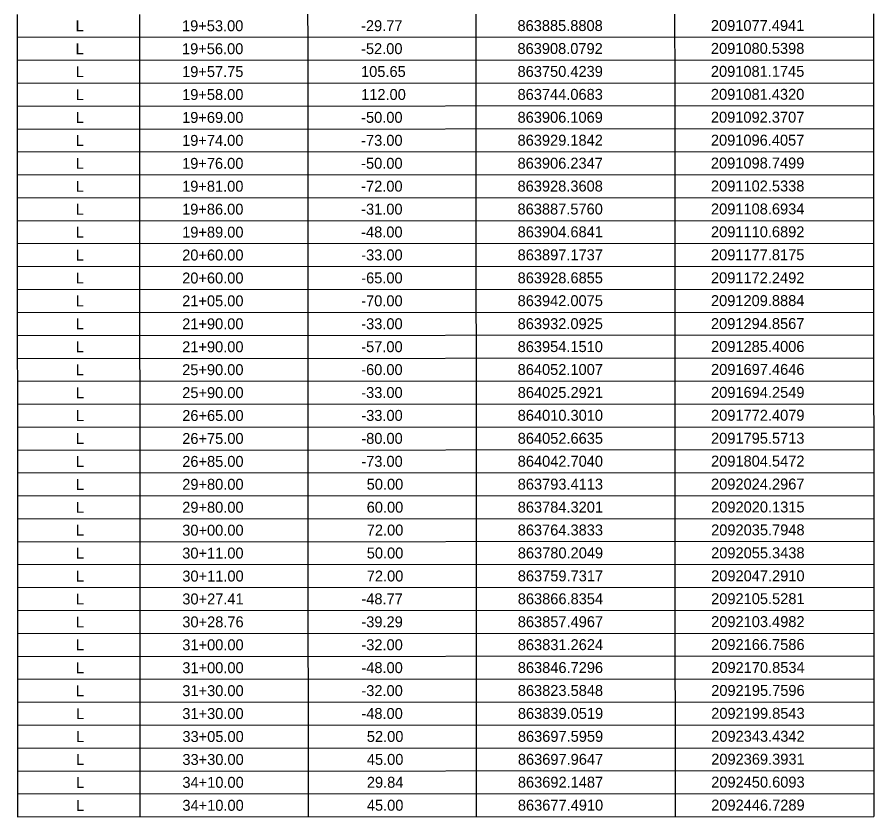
# Model space of a CAD drawing. Extents: x 2093228 to 2098328, y 861854 to 865154.
# Drawn here: x 2094060 to 2095157, y 863101 to 864125 of the extents above; entities that cross this region are included whole.
import ezdxf

# ---------------------------------------------------------------- set-up
doc = ezdxf.new("R2010")
doc.units = 0
doc.layers.add('CTL Sheet Table Cell', color=7, linetype='Continuous')
doc.layers.add('CTL Sheet Text', color=7, linetype='Continuous')

msp = doc.modelspace()

# ---------------------------------------------------------------- linework, layer by layer
at = {"layer": 'CTL Sheet Table Cell'}
for p, q in [((2094060, 864128.6), (2094060, 864099.2)), ((2094216.6, 864128.6), (2094216.6, 864099.3)), ((2094431.9, 864128.7), (2094432, 864099.4)), ((2094647.3, 864128.9), (2094647.3, 864099.5)), ((2094901.7, 864129), (2094901.7, 864099.6)), ((2095156.2, 864129.1), (2095156.2, 864099.7)), ((2094060, 864099.2), (2095156.2, 864099.7)), ((2094060, 864099.2), (2094060.1, 864069.8)), ((2094216.6, 864099.3), (2094216.7, 864069.9)), ((2094432, 864099.4), (2094432, 864070)), ((2094647.3, 864099.5), (2094647.3, 864070.1)), ((2094901.7, 864099.6), (2094901.8, 864070.3)), ((2095156.2, 864099.7), (2095156.2, 864070.4)), ((2094060.1, 864069.8), (2095156.2, 864070.4)), ((2094060.1, 864069.8), (2094060.1, 864040.5)), ((2094216.7, 864069.9), (2094216.7, 864040.6)), ((2094432, 864070), (2094432, 864040.7)), ((2094647.3, 864070.1), (2094647.3, 864040.8)), ((2094901.8, 864070.3), (2094901.8, 864040.9)), ((2095156.2, 864070.4), (2095156.2, 864041)), ((2094060.1, 864040.5), (2095156.2, 864041)), ((2094060.1, 864040.5), (2094060.1, 864011.1)), ((2094216.7, 864040.6), (2094216.7, 864011.2)), ((2094432, 864040.7), (2094432, 864011.3)), ((2094647.3, 864040.8), (2094647.3, 864011.4)), ((2094901.8, 864040.9), (2094901.8, 864011.5)), ((2095156.2, 864041), (2095156.3, 864011.7)), ((2094060.1, 864011.1), (2095156.3, 864011.7)), ((2094060.1, 864011.1), (2094060.1, 863981.8)), ((2094216.7, 864011.2), (2094216.7, 863981.8)), ((2094432, 864011.3), (2094432, 863981.9)), ((2094647.3, 864011.4), (2094647.3, 863982)), ((2094901.8, 864011.5), (2094901.8, 863982.2)), ((2095156.3, 864011.7), (2095156.3, 863982.3)), ((2094060.1, 863981.8), (2095156.3, 863982.3)), ((2094060.1, 863981.8), (2094060.1, 863952.4)), ((2094216.7, 863981.8), (2094216.7, 863952.5)), ((2094432, 863981.9), (2094432, 863952.6)), ((2094647.3, 863982), (2094647.4, 863952.7)), ((2094901.8, 863982.2), (2094901.8, 863952.8)), ((2095156.3, 863982.3), (2095156.3, 863952.9)), ((2094060.1, 863952.4), (2095156.3, 863952.9)), ((2094060.1, 863952.4), (2094060.1, 863923)), ((2094216.7, 863952.5), (2094216.7, 863923.1)), ((2094432, 863952.6), (2094432, 863923.2)), ((2094647.4, 863952.7), (2094647.4, 863923.3)), ((2094901.8, 863952.8), (2094901.8, 863923.4)), ((2095156.3, 863952.9), (2095156.3, 863923.6)), ((2094060.1, 863923), (2095156.3, 863923.6)), ((2094060.1, 863923), (2094060.1, 863893.7)), ((2094216.7, 863923.1), (2094216.7, 863893.8)), ((2094432, 863923.2), (2094432.1, 863893.9)), ((2094647.4, 863923.3), (2094647.4, 863894)), ((2094901.8, 863923.4), (2094901.8, 863894.1)), ((2095156.3, 863923.6), (2095156.3, 863894.2)), ((2094060.1, 863893.7), (2095156.3, 863894.2)), ((2094901.8, 863894.1), (2094901.9, 863864.7)), ((2095156.3, 863894.2), (2095156.3, 863864.8)), ((2094060.1, 863893.7), (2094060.2, 863864.3)), ((2094216.7, 863893.8), (2094216.8, 863864.4)), ((2094432.1, 863893.9), (2094432.1, 863864.5)), ((2094647.4, 863894), (2094647.4, 863864.6)), ((2094060.2, 863864.3), (2095156.3, 863864.8)), ((2094060.2, 863864.3), (2094060.2, 863835)), ((2094216.8, 863864.4), (2094216.8, 863835)), ((2094432.1, 863864.5), (2094432.1, 863835.1)), ((2094647.4, 863864.6), (2094647.4, 863835.2)), ((2094901.9, 863864.7), (2094901.9, 863835.4)), ((2095156.3, 863864.8), (2095156.3, 863835.5)), ((2094060.2, 863835), (2095156.3, 863835.5)), ((2094060.2, 863835), (2094060.2, 863805.6)), ((2094216.8, 863835), (2094216.8, 863805.7)), ((2094432.1, 863835.1), (2094432.1, 863805.8)), ((2094647.4, 863835.2), (2094647.4, 863805.9)), ((2094901.9, 863835.4), (2094901.9, 863806)), ((2095156.3, 863835.5), (2095156.4, 863806.1)), ((2094060.2, 863805.6), (2095156.4, 863806.1)), ((2094060.2, 863805.6), (2094060.2, 863776.2)), ((2094216.8, 863805.7), (2094216.8, 863776.3)), ((2094432.1, 863805.8), (2094432.1, 863776.4)), ((2094647.4, 863805.9), (2094647.4, 863776.5)), ((2094901.9, 863806), (2094901.9, 863776.6)), ((2095156.4, 863806.1), (2095156.4, 863776.8)), ((2094060.2, 863776.2), (2095156.4, 863776.8)), ((2094060.2, 863776.2), (2094060.2, 863746.9)), ((2094216.8, 863776.3), (2094216.8, 863746.9)), ((2094432.1, 863776.4), (2094432.1, 863747)), ((2094647.4, 863776.5), (2094647.4, 863747.2)), ((2094901.9, 863776.6), (2094901.9, 863747.3)), ((2095156.4, 863776.8), (2095156.4, 863747.4)), ((2094060.2, 863746.9), (2095156.4, 863747.4)), ((2094060.2, 863746.9), (2094060.2, 863717.5)), ((2094216.8, 863746.9), (2094216.8, 863717.6)), ((2094432.1, 863747), (2094432.1, 863717.7)), ((2094647.4, 863747.2), (2094647.5, 863717.8)), ((2094901.9, 863747.3), (2094901.9, 863717.9)), ((2095156.4, 863747.4), (2095156.4, 863718)), ((2094060.2, 863717.5), (2095156.4, 863718)), ((2094060.2, 863717.5), (2094060.2, 863688.1)), ((2094216.8, 863717.6), (2094216.8, 863688.2)), ((2094432.1, 863717.7), (2094432.2, 863688.3)), ((2094647.5, 863717.8), (2094647.5, 863688.4)), ((2094901.9, 863717.9), (2094901.9, 863688.6)), ((2095156.4, 863718), (2095156.4, 863688.7)), ((2094060.2, 863688.1), (2095156.4, 863688.7)), ((2094060.2, 863688.1), (2094060.3, 863658.8)), ((2094216.8, 863688.2), (2094216.9, 863658.9)), ((2094432.2, 863688.3), (2094432.2, 863659)), ((2094647.5, 863688.4), (2094647.5, 863659.1)), ((2094901.9, 863688.6), (2094902, 863659.2)), ((2095156.4, 863688.7), (2095156.4, 863659.3)), ((2094060.3, 863658.8), (2095156.4, 863659.3)), ((2094060.3, 863658.8), (2094060.3, 863629.4)), ((2094216.9, 863658.9), (2094216.9, 863629.5)), ((2094432.2, 863659), (2094432.2, 863629.6)), ((2094647.5, 863659.1), (2094647.5, 863629.7)), ((2094902, 863659.2), (2094902, 863629.8)), ((2095156.4, 863659.3), (2095156.4, 863630)), ((2094060.3, 863629.4), (2095156.4, 863630)), ((2094060.3, 863629.4), (2094060.3, 863600.1)), ((2094216.9, 863629.5), (2094216.9, 863600.1)), ((2094432.2, 863629.6), (2094432.2, 863600.2)), ((2094647.5, 863629.7), (2094647.5, 863600.3)), ((2094902, 863629.8), (2094902, 863600.5)), ((2095156.4, 863630), (2095156.5, 863600.6)), ((2094060.3, 863600.1), (2095156.5, 863600.6)), ((2094060.3, 863600.1), (2094060.3, 863570.7)), ((2094216.9, 863600.1), (2094216.9, 863570.8)), ((2094432.2, 863600.2), (2094432.2, 863570.9)), ((2094647.5, 863600.3), (2094647.5, 863571)), ((2094902, 863600.5), (2094902, 863571.1)), ((2095156.5, 863600.6), (2095156.5, 863571.2)), ((2094060.3, 863570.7), (2095156.5, 863571.2)), ((2094060.3, 863570.7), (2094060.3, 863541.3)), ((2094216.9, 863570.8), (2094216.9, 863541.4)), ((2094432.2, 863570.9), (2094432.2, 863541.5)), ((2094647.5, 863571), (2094647.5, 863541.6)), ((2094902, 863571.1), (2094902, 863541.7)), ((2095156.5, 863571.2), (2095156.5, 863541.9)), ((2094060.3, 863541.3), (2095156.5, 863541.9)), ((2094060.3, 863541.3), (2094060.3, 863512)), ((2094216.9, 863541.4), (2094216.9, 863512.1)), ((2094432.2, 863541.5), (2094432.2, 863512.2)), ((2094647.5, 863541.6), (2094647.6, 863512.3)), ((2094902, 863541.7), (2094902, 863512.4)), ((2095156.5, 863541.9), (2095156.5, 863512.5)), ((2094060.3, 863512), (2095156.5, 863512.5)), ((2094060.3, 863512), (2094060.3, 863482.6)), ((2094216.9, 863512.1), (2094216.9, 863482.7)), ((2094432.2, 863512.2), (2094432.3, 863482.8)), ((2094647.6, 863512.3), (2094647.6, 863482.9)), ((2094902, 863512.4), (2094902, 863483)), ((2095156.5, 863512.5), (2095156.5, 863483.1)), ((2094060.3, 863482.6), (2095156.5, 863483.1)), ((2094060.3, 863482.6), (2094060.4, 863453.3)), ((2094216.9, 863482.7), (2094217, 863453.3)), ((2094432.3, 863482.8), (2094432.3, 863453.4)), ((2094647.6, 863482.9), (2094647.6, 863453.5)), ((2094902, 863483), (2094902.1, 863453.7)), ((2095156.5, 863483.1), (2095156.5, 863453.8)), ((2094060.4, 863453.3), (2095156.5, 863453.8)), ((2094060.4, 863453.3), (2094060.4, 863423.9)), ((2094217, 863453.3), (2094217, 863424)), ((2094432.3, 863453.4), (2094432.3, 863424.1)), ((2094647.6, 863453.5), (2094647.6, 863424.2)), ((2094902.1, 863453.7), (2094902.1, 863424.3)), ((2095156.5, 863453.8), (2095156.5, 863424.4)), ((2094060.4, 863423.9), (2095156.5, 863424.4)), ((2094060.4, 863423.9), (2094060.4, 863394.5)), ((2094217, 863424), (2094217, 863394.6)), ((2094432.3, 863424.1), (2094432.3, 863394.7)), ((2094647.6, 863424.2), (2094647.6, 863394.8)), ((2094902.1, 863424.3), (2094902.1, 863394.9)), ((2095156.5, 863424.4), (2095156.6, 863395.1)), ((2094060.4, 863394.5), (2095156.6, 863395.1)), ((2094060.4, 863394.5), (2094060.4, 863365.2)), ((2094217, 863394.6), (2094217, 863365.2)), ((2094432.3, 863394.7), (2094432.3, 863365.3)), ((2094647.6, 863394.8), (2094647.6, 863365.5)), ((2094902.1, 863394.9), (2094902.1, 863365.6)), ((2095156.6, 863395.1), (2095156.6, 863365.7)), ((2094060.4, 863365.2), (2095156.6, 863365.7)), ((2094060.4, 863365.2), (2094060.4, 863335.8)), ((2094217, 863365.2), (2094217, 863335.9)), ((2094432.3, 863365.3), (2094432.3, 863336)), ((2094647.6, 863365.5), (2094647.6, 863336.1)), ((2094902.1, 863365.6), (2094902.1, 863336.2)), ((2095156.6, 863365.7), (2095156.6, 863336.3)), ((2094060.4, 863335.8), (2095156.6, 863336.3)), ((2094060.4, 863335.8), (2094060.4, 863306.4)), ((2094217, 863335.9), (2094217, 863306.5)), ((2094432.3, 863336), (2094432.3, 863306.6)), ((2094647.6, 863336.1), (2094647.7, 863306.7)), ((2094902.1, 863336.2), (2094902.1, 863306.9)), ((2095156.6, 863336.3), (2095156.6, 863307)), ((2094060.4, 863306.4), (2095156.6, 863307)), ((2094060.4, 863306.4), (2094060.4, 863277.1)), ((2094217, 863306.5), (2094217, 863277.2)), ((2094432.3, 863306.6), (2094432.4, 863277.3)), ((2094647.7, 863306.7), (2094647.7, 863277.4)), ((2094902.1, 863306.9), (2094902.1, 863277.5)), ((2095156.6, 863307), (2095156.6, 863277.6)), ((2094060.4, 863277.1), (2095156.6, 863277.6)), ((2094060.4, 863277.1), (2094060.5, 863247.7)), ((2094217, 863277.2), (2094217.1, 863247.8)), ((2094432.4, 863277.3), (2094432.4, 863247.9)), ((2094647.7, 863277.4), (2094647.7, 863248)), ((2094902.1, 863277.5), (2094902.2, 863248.1)), ((2095156.6, 863277.6), (2095156.6, 863248.2)), ((2094060.5, 863247.7), (2095156.6, 863248.2)), ((2094060.5, 863247.7), (2094060.5, 863218.4)), ((2094217.1, 863247.8), (2094217.1, 863218.4)), ((2094432.4, 863247.9), (2094432.4, 863218.5)), ((2094647.7, 863248), (2094647.7, 863218.6)), ((2094902.2, 863248.1), (2094902.2, 863218.8)), ((2095156.6, 863248.2), (2095156.6, 863218.9)), ((2094060.5, 863218.4), (2095156.6, 863218.9)), ((2094060.5, 863218.4), (2094060.5, 863189)), ((2094217.1, 863218.4), (2094217.1, 863189.1)), ((2094432.4, 863218.5), (2094432.4, 863189.2)), ((2094647.7, 863218.6), (2094647.7, 863189.3)), ((2094902.2, 863218.8), (2094902.2, 863189.4)), ((2095156.6, 863218.9), (2095156.7, 863189.5)), ((2094060.5, 863189), (2095156.7, 863189.5)), ((2094060.5, 863189), (2094060.5, 863159.6)), ((2094217.1, 863189.1), (2094217.1, 863159.7)), ((2094432.4, 863189.2), (2094432.4, 863159.8)), ((2094647.7, 863189.3), (2094647.7, 863159.9)), ((2094902.2, 863189.4), (2094902.2, 863160)), ((2095156.7, 863189.5), (2095156.7, 863160.2)), ((2094060.5, 863159.6), (2095156.7, 863160.2)), ((2094060.5, 863159.6), (2094060.5, 863130.3)), ((2094217.1, 863159.7), (2094217.1, 863130.4)), ((2094432.4, 863159.8), (2094432.4, 863130.5)), ((2094647.7, 863159.9), (2094647.7, 863130.6)), ((2094902.2, 863160), (2094902.2, 863130.7)), ((2095156.7, 863160.2), (2095156.7, 863130.8)), ((2094060.5, 863130.3), (2095156.7, 863130.8)), ((2094060.5, 863130.3), (2094060.5, 863100.9)), ((2094217.1, 863130.4), (2094217.1, 863101)), ((2094432.4, 863130.5), (2094432.4, 863101.1)), ((2094647.7, 863130.6), (2094647.8, 863101.2)), ((2094902.2, 863130.7), (2094902.2, 863101.3)), ((2095156.7, 863130.8), (2095156.7, 863101.4)), ((2094060.5, 863100.9), (2095156.7, 863101.4))]:
    msp.add_line(p, q, dxfattribs=at)

# ---------------------------------------------------------------- texts
at = {"layer": 'CTL Sheet Text'}
for s, height, p in [('L', 14, (2094134.9, 864106.9)), ('19+53.00', 13.98, (2094271.1, 864107)), ('-29.77', 13.98, (2094500.3, 864107.1)), ('863885.8808', 13.982, (2094700.5, 864107.2)), ('2091077.4941', 13.982, (2094948.1, 864107.3)), ('L', 14, (2094134.9, 864077.6)), ('19+56.00', 13.98, (2094271.1, 864077.6)), ('-52.00', 13.98, (2094500.3, 864077.7)), ('863908.0792', 13.982, (2094700.5, 864077.8)), ('2091080.5398', 13.982, (2094948.1, 864078)), ('L', 14, (2094135, 864048.2)), ('19+57.75', 13.98, (2094271.2, 864048.3)), ('105.65', 13.98, (2094500.3, 864048.4)), ('863750.4239', 13.982, (2094700.6, 864048.5)), ('2091081.1745', 13.982, (2094948.1, 864048.6)), ('L', 14, (2094135, 864018.8)), ('19+58.00', 13.98, (2094271.2, 864018.9)), ('112.00', 13.98, (2094500.4, 864019)), ('863744.0683', 13.982, (2094700.6, 864019.1)), ('2091081.4320', 13.982, (2094948.1, 864019.2)), ('19+69.00', 13.98, (2094271.2, 863989.6)), ('-50.00', 13.98, (2094500.4, 863989.7)), ('863906.1069', 13.982, (2094700.6, 863989.8)), ('2091092.3707', 13.982, (2094948.1, 863989.9)), ('L', 14, (2094135, 863989.5)), ('L', 14, (2094135, 863960.1)), ('19+74.00', 13.98, (2094271.2, 863960.2)), ('-73.00', 13.98, (2094500.4, 863960.3)), ('863929.1842', 13.982, (2094700.6, 863960.4)), ('2091096.4057', 13.982, (2094948.1, 863960.5)), ('L', 14, (2094135, 863930.8)), ('19+76.00', 13.98, (2094271.2, 863930.8)), ('-50.00', 13.98, (2094500.4, 863930.9)), ('863906.2347', 13.982, (2094700.6, 863931)), ('2091098.7499', 13.982, (2094948.1, 863931.2)), ('2091102.5338', 13.982, (2094948.2, 863901.8)), ('L', 14, (2094135, 863901.4)), ('19+81.00', 13.98, (2094271.2, 863901.5)), ('-72.00', 13.98, (2094500.4, 863901.6)), ('863928.3608', 13.982, (2094700.6, 863901.7)), ('L', 14, (2094135, 863872)), ('19+86.00', 13.98, (2094271.2, 863872.1)), ('-31.00', 13.98, (2094500.4, 863872.2)), ('863887.5760', 13.982, (2094700.6, 863872.3)), ('2091108.6934', 13.982, (2094948.2, 863872.4)), ('L', 14, (2094135.1, 863842.7)), ('19+89.00', 13.98, (2094271.3, 863842.7)), ('-48.00', 13.98, (2094500.4, 863842.9)), ('863904.6841', 13.982, (2094700.7, 863843)), ('2091110.6892', 13.982, (2094948.2, 863843.1)), ('L', 14, (2094135.1, 863813.3)), ('20+60.00', 13.98, (2094271.3, 863813.4)), ('-33.00', 13.98, (2094500.5, 863813.5)), ('863897.1737', 13.982, (2094700.7, 863813.6)), ('2091177.8175', 13.982, (2094948.2, 863813.7)), ('L', 14, (2094135.1, 863784)), ('20+60.00', 13.98, (2094271.3, 863784)), ('-65.00', 13.98, (2094500.5, 863784.1)), ('863928.6855', 13.982, (2094700.7, 863784.2)), ('2091172.2492', 13.982, (2094948.2, 863784.3)), ('L', 14, (2094135.1, 863754.6)), ('21+05.00', 13.98, (2094271.3, 863754.7)), ('-70.00', 13.98, (2094500.5, 863754.8)), ('863942.0075', 13.982, (2094700.7, 863754.9)), ('2091209.8884', 13.982, (2094948.2, 863755)), ('L', 14, (2094135.1, 863725.2)), ('21+90.00', 13.98, (2094271.3, 863725.3)), ('-33.00', 13.98, (2094500.5, 863725.4)), ('863932.0925', 13.982, (2094700.7, 863725.5)), ('2091294.8567', 13.982, (2094948.2, 863725.6)), ('L', 14, (2094135.1, 863695.9)), ('21+90.00', 13.98, (2094271.3, 863695.9)), ('-57.00', 13.98, (2094500.5, 863696)), ('863954.1510', 13.982, (2094700.7, 863696.1)), ('2091285.4006', 13.982, (2094948.3, 863696.3)), ('L', 14, (2094135.1, 863666.5)), ('25+90.00', 13.98, (2094271.3, 863666.6)), ('-60.00', 13.98, (2094500.5, 863666.7)), ('864052.1007', 13.982, (2094700.7, 863666.8)), ('2091697.4646', 13.982, (2094948.3, 863666.9)), ('L', 14, (2094135.2, 863637.1)), ('25+90.00', 13.98, (2094271.4, 863637.2)), ('-33.00', 13.98, (2094500.5, 863637.3)), ('864025.2921', 13.982, (2094700.8, 863637.4)), ('2091694.2549', 13.982, (2094948.3, 863637.5)), ('L', 14, (2094135.2, 863607.8)), ('26+65.00', 13.98, (2094271.4, 863607.9)), ('-33.00', 13.98, (2094500.6, 863608)), ('864010.3010', 13.982, (2094700.8, 863608.1)), ('2091772.4079', 13.982, (2094948.3, 863608.2)), ('L', 14, (2094135.2, 863578.4)), ('26+75.00', 13.98, (2094271.4, 863578.5)), ('-80.00', 13.98, (2094500.6, 863578.6)), ('864052.6635', 13.982, (2094700.8, 863578.7)), ('2091795.5713', 13.982, (2094948.3, 863578.8)), ('L', 14, (2094135.2, 863549.1)), ('26+85.00', 13.98, (2094271.4, 863549.1)), ('-73.00', 13.98, (2094500.6, 863549.2)), ('864042.7040', 13.982, (2094700.8, 863549.3)), ('2091804.5472', 13.982, (2094948.3, 863549.5)), ('L', 14, (2094135.2, 863519.7)), ('29+80.00', 13.98, (2094271.4, 863519.8)), ('50.00', 13.98, (2094507.5, 863519.9)), ('863793.4113', 13.982, (2094700.8, 863520)), ('2092024.2967', 13.982, (2094948.3, 863520.1)), ('L', 14, (2094135.2, 863490.3)), ('29+80.00', 13.98, (2094271.4, 863490.4)), ('60.00', 13.98, (2094507.5, 863490.5)), ('863784.3201', 13.982, (2094700.8, 863490.6)), ('2092020.1315', 13.982, (2094948.4, 863490.7)), ('L', 14, (2094135.2, 863461)), ('30+00.00', 13.98, (2094271.4, 863461)), ('72.00', 13.98, (2094507.6, 863461.2)), ('863764.3833', 13.982, (2094700.8, 863461.3)), ('2092035.7948', 13.982, (2094948.4, 863461.4)), ('L', 14, (2094135.3, 863431.6)), ('30+11.00', 13.98, (2094271.4, 863431.7)), ('50.00', 13.98, (2094507.6, 863431.8)), ('863780.2049', 13.982, (2094700.9, 863431.9)), ('2092055.3438', 13.982, (2094948.4, 863432)), ('L', 14, (2094135.3, 863402.3)), ('30+11.00', 13.98, (2094271.5, 863402.3)), ('72.00', 13.98, (2094507.6, 863402.4)), ('863759.7317', 13.982, (2094700.9, 863402.5)), ('2092047.2910', 13.982, (2094948.4, 863402.6)), ('L', 14, (2094135.3, 863372.9)), ('30+27.41', 13.98, (2094271.5, 863373)), ('-48.77', 13.98, (2094500.7, 863373.1)), ('863866.8354', 13.982, (2094700.9, 863373.2)), ('2092105.5281', 13.982, (2094948.4, 863373.3)), ('L', 14, (2094135.3, 863343.5)), ('30+28.76', 13.98, (2094271.5, 863343.6)), ('-39.29', 13.98, (2094500.7, 863343.7)), ('863857.4967', 13.982, (2094700.9, 863343.8)), ('2092103.4982', 13.982, (2094948.4, 863343.9)), ('L', 14, (2094135.3, 863314.2)), ('31+00.00', 13.98, (2094271.5, 863314.2)), ('-32.00', 13.98, (2094500.7, 863314.3)), ('863831.2624', 13.982, (2094700.9, 863314.4)), ('2092166.7586', 13.982, (2094948.4, 863314.6)), ('L', 14, (2094135.3, 863284.8)), ('31+00.00', 13.98, (2094271.5, 863284.9)), ('-48.00', 13.98, (2094500.7, 863285)), ('863846.7296', 13.982, (2094700.9, 863285.1)), ('2092170.8534', 13.982, (2094948.5, 863285.2)), ('L', 14, (2094135.3, 863255.4)), ('31+30.00', 13.98, (2094271.5, 863255.5)), ('-32.00', 13.98, (2094500.7, 863255.6)), ('863823.5848', 13.982, (2094700.9, 863255.7)), ('2092195.7596', 13.982, (2094948.5, 863255.8)), ('L', 14, (2094135.4, 863226.1)), ('31+30.00', 13.98, (2094271.5, 863226.2)), ('-48.00', 13.98, (2094500.7, 863226.3)), ('863839.0519', 13.982, (2094701, 863226.4)), ('2092199.8543', 13.982, (2094948.5, 863226.5)), ('L', 14, (2094135.4, 863196.7)), ('33+05.00', 13.98, (2094271.6, 863196.8)), ('52.00', 13.98, (2094507.7, 863196.9)), ('863697.5959', 13.982, (2094701, 863197)), ('2092343.4342', 13.982, (2094948.5, 863197.1)), ('L', 14, (2094135.4, 863167.4)), ('33+30.00', 13.98, (2094271.6, 863167.4)), ('45.00', 13.98, (2094507.7, 863167.5)), ('863697.9647', 13.982, (2094701, 863167.6)), ('2092369.3931', 13.982, (2094948.5, 863167.8)), ('L', 14, (2094135.4, 863138)), ('34+10.00', 13.98, (2094271.6, 863138.1)), ('29.84', 13.98, (2094507.7, 863138.2)), ('863692.1487', 13.982, (2094701, 863138.3)), ('2092450.6093', 13.982, (2094948.5, 863138.4)), ('L', 14, (2094135.4, 863108.6)), ('34+10.00', 13.98, (2094271.6, 863108.7)), ('45.00', 13.98, (2094507.7, 863108.8)), ('863677.4910', 13.982, (2094701, 863108.9)), ('2092446.7289', 13.982, (2094948.5, 863109))]:
    msp.add_text(s, height=height, rotation=0.0276, dxfattribs=at).set_placement(p)

doc.saveas('drawing.dxf')
